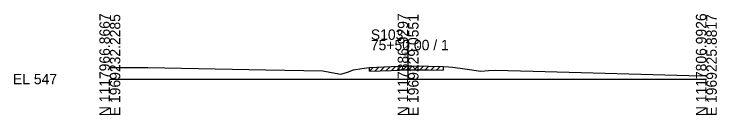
# Model space of a CAD drawing. Extents: x -26 to 163, y -10 to 24018.
# Drawn here: x -25.7 to 162.8, y 23490.3 to 23517.5 of the extents above; entities that cross this region are included whole.
import ezdxf

# ---------------------------------------------------------------- set-up
doc = ezdxf.new("R2010")
doc.units = 0
for name, color, linetype in [('RD_GPK_XS_Cell', 7, 'Continuous'), ('RD_XS_ExGround', 7, 'Continuous'), ('RD_XS_ExPaveRet', 7, 'Continuous'), ('RD_XS_TX_Elev_EX', 7, 'Continuous')]:
    doc.layers.add(name, color=color, linetype=linetype)

msp = doc.modelspace()

# ---------------------------------------------------------------- linework, layer by layer
at = {"layer": 'RD_GPK_XS_Cell'}
for p, q in [((80, 23500), (80, 23510.56)), ((0, 23500), (80, 23500)), ((80, 23500), (160, 23500))]:
    msp.add_line(p, q, dxfattribs=at)
at = {"layer": 'RD_XS_ExGround'}
msp.add_lwpolyline([(0, 23503.1), (10.17, 23503.1), (41.81, 23502.44), (57.16, 23502.19), (59.45, 23501.75), (61.99, 23501.27), (63.71, 23501.87), (65.35, 23502.46), (67.59, 23502.8), (69.61, 23503.1), (75.45, 23503.34), (80, 23503.51), (80.31, 23503.52), (85.5, 23503.45), (89.42, 23503.37), (90.88, 23503.26), (91.96, 23503.17), (95.25, 23502.73), (99.55, 23502.14), (101.58, 23502.3), (103.35, 23502.43), (113.56, 23502.11), (158.55, 23500.86), (160, 23501.02)], dxfattribs=at)
at = {"layer": 'RD_XS_ExPaveRet'}
for p, q in [((69.61, 23502.1), (70.65, 23503.14)), ((69.61, 23502.1), (69.61, 23503.1)), ((71.11, 23502.16), (72.15, 23503.2)), ((72.61, 23502.22), (73.65, 23503.27)), ((74.11, 23502.29), (75.15, 23503.33)), ((75.45, 23502.34), (80, 23502.51)), ((75.61, 23502.35), (76.65, 23503.39)), ((77.11, 23502.4), (78.15, 23503.44)), ((78.61, 23502.46), (79.65, 23503.5)), ((80, 23502.51), (80.31, 23502.52)), ((80.11, 23502.51), (81.11, 23503.51)), ((80.31, 23502.52), (85.5, 23502.45)), ((81.61, 23502.5), (82.6, 23503.49)), ((83.11, 23502.48), (84.1, 23503.47)), ((84.61, 23502.46), (85.6, 23503.44)), ((86.11, 23502.43), (87.09, 23503.42)), ((87.61, 23502.41), (88.59, 23503.39)), ((89.42, 23503.37), (89.42, 23502.37)), ((69.61, 23502.1), (75.45, 23502.34)), ((85.5, 23502.45), (89.42, 23502.37))]:
    msp.add_line(p, q, dxfattribs=at)

# ---------------------------------------------------------------- texts
at = {"layer": 'RD_GPK_XS_Cell'}
for s, p in [('N 1117966.8667', (0, 23490)), ('E 1969232.2285', (2.8, 23490)), ('N 1117886.9297', (80, 23490)), ('E 1969229.0551', (82.8, 23490)), ('N 1117806.9926', (160, 23490)), ('E 1969225.8817', (162.8, 23490))]:
    msp.add_text(s, height=2.8, rotation=90, dxfattribs=at).set_placement(p)
for s, p in [('S103', (70, 23510.56)), ('75+50.00 / 1', (70, 23507.76)), ('EL 547', (-26, 23498.6))]:
    msp.add_text(s, height=2.8, dxfattribs=at).set_placement(p)
at = {"layer": 'RD_XS_TX_Elev_EX'}
msp.add_text('550.51', height=0.8, rotation=90, dxfattribs=at).set_placement((79.9, 23505.51))

doc.saveas('drawing.dxf')
